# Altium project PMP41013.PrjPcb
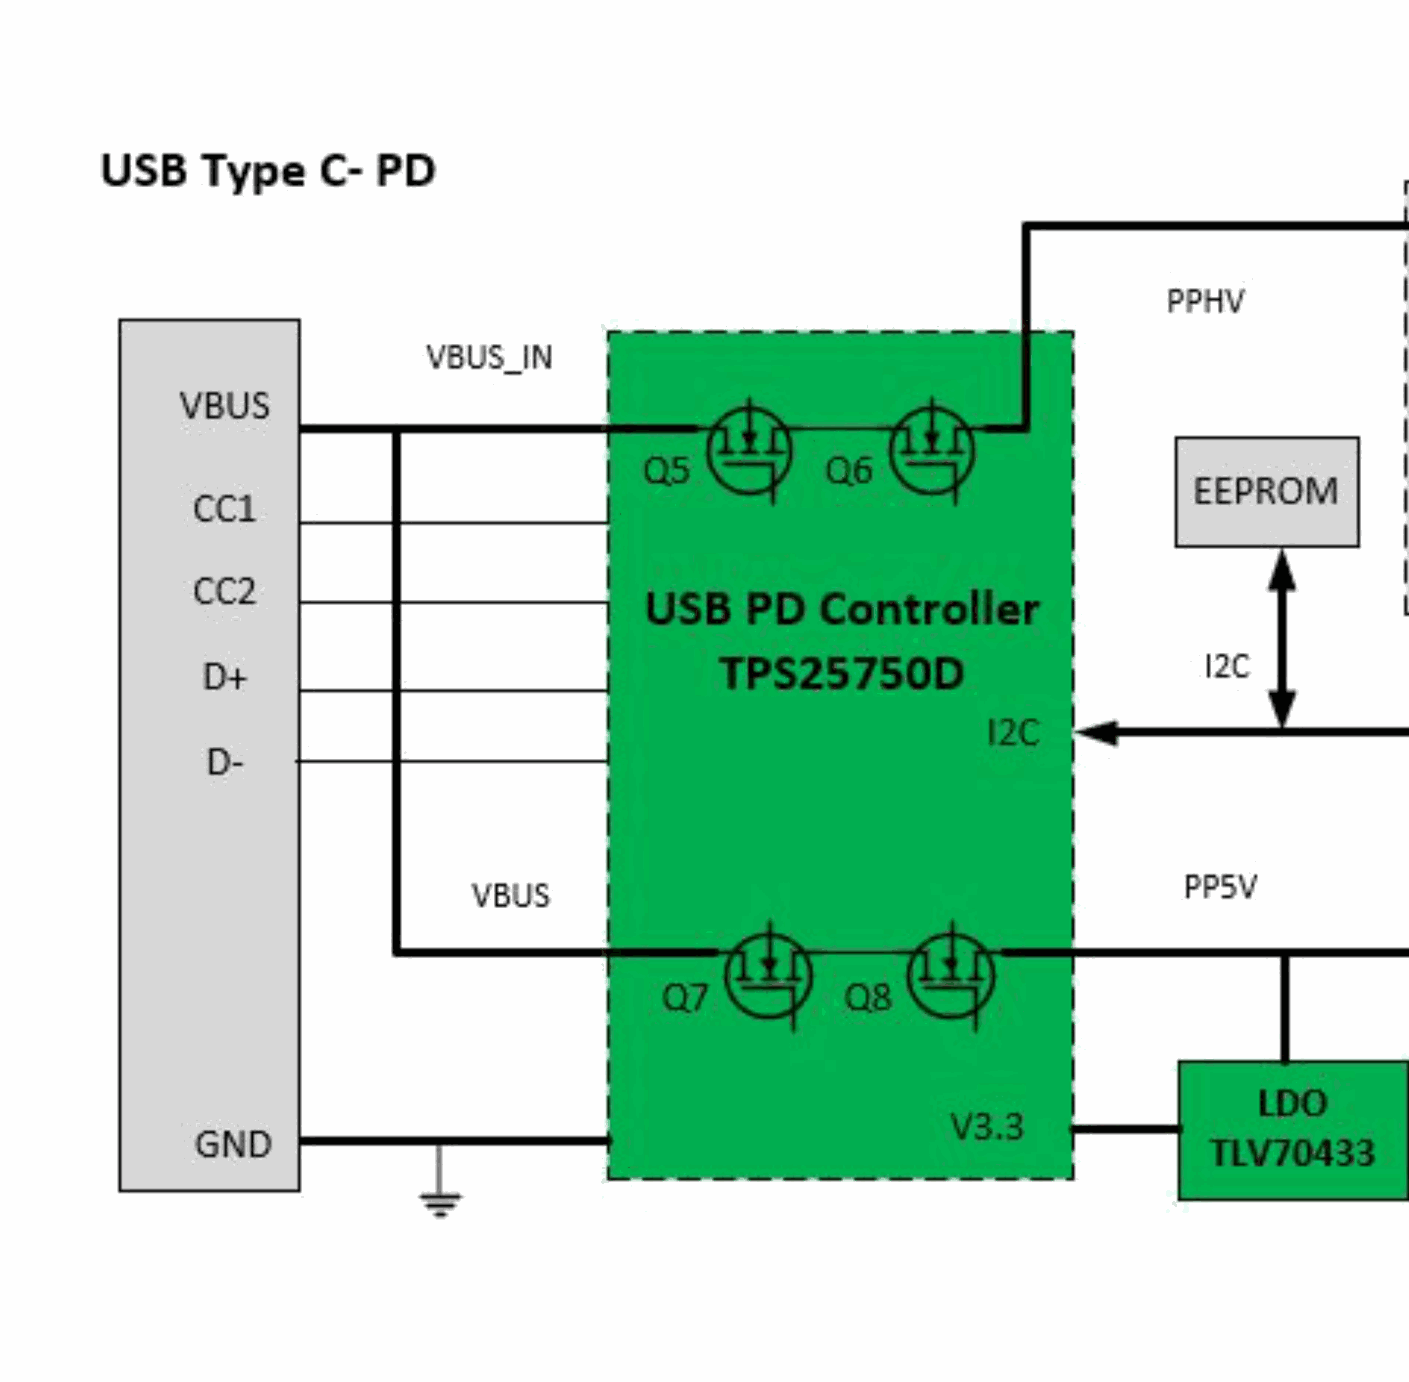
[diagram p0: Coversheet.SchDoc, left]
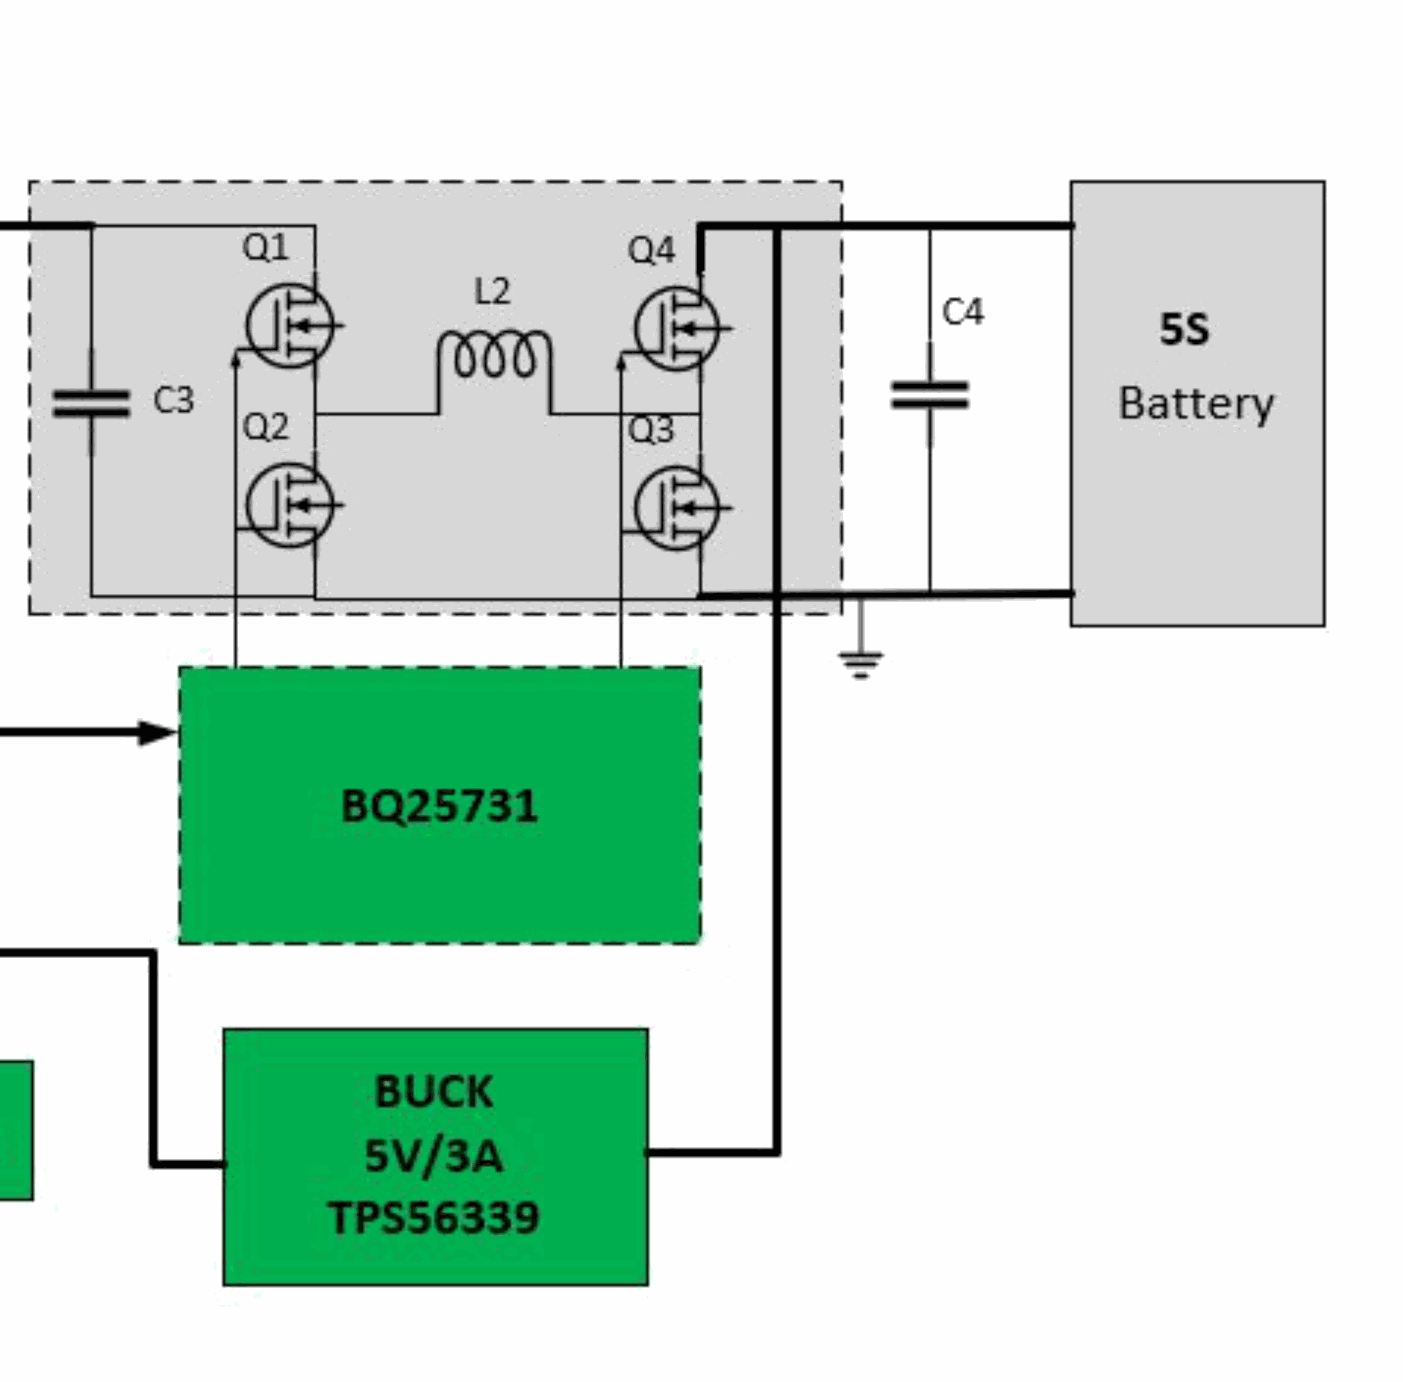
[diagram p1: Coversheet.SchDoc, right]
TID: N/A; TechSupport: http://www.ti.com/support; SCH_Rev: E1; PRJ_Title: 5S Bi-directional USB Type C PD charger; PRJ_Number: PMP41013; PRJ_Engineer: Max Wang; PRJ_Customer: Public Release; PCB_Rev: E1; PCB_Layout: Max Wang; CopyrightYear: 2018
4 sheets, 135 parts. Net scope: global (net labels, ports and power ports of the same name join across sheets).
Board file: PMP41013.PcbDoc
Sheets:
  Coversheet.SchDoc
  BQ25731 Charger.SchDoc
  TPS25750 USB PD Control.SchDoc
  PMP41013_Hardware.SchDoc

## Sheet Coversheet.SchDoc
size A2; Date: Not shown in title block; ApprovedBy: Not shown in title block; CheckedBy: Not shown in title block; Author: Not shown in title block; CompanyName: Not shown in title block; Engineer: Not shown in title block; Organization: Not shown in title block; Address1: Not shown in title block; Address2: Not shown in title block; Address3: Not shown in title block; Address4: Not shown in title block; DocumentNumber: 2; Revision: Use project parameter SCH_Rev; SheetNumber: 2; SheetTotal: 3; PageSetup: Record=PageOptions¦CenterHorizontal=True¦CenterVertical=True¦PrintScale=1.00¦XCorrection=1.00¦YCorrection=1.00¦PrintKind=0¦BorderSize=5000000¦LeftOffset=0¦BottomOffset=0¦Orientation=2¦PaperLength=1000¦PaperWidth=1000¦Scale=100¦PaperSource=15¦PrintQuality=600¦MediaType=1¦DitherType=10¦PaperKind=Letter¦PrintScaleMode=1

## Sheet BQ25731 Charger.SchDoc
size A2; DrawnBy: Max Wang; Engineer: Max Wang; PageSetup: Record=PageOptions¦CenterHorizontal=True¦CenterVertical=True¦PrintScale=0.69¦XCorrection=1.00¦YCorrection=1.00¦PrintKind=0¦BorderSize=5000000¦LeftOffset=0¦BottomOffset=0¦Orientation=2¦PaperLength=1000¦PaperWidth=1000¦Scale=100¦PaperSource=15¦PrintQuality=600¦MediaType=1¦DitherType=10¦PaperKind=Letter¦PrintScaleMode=1
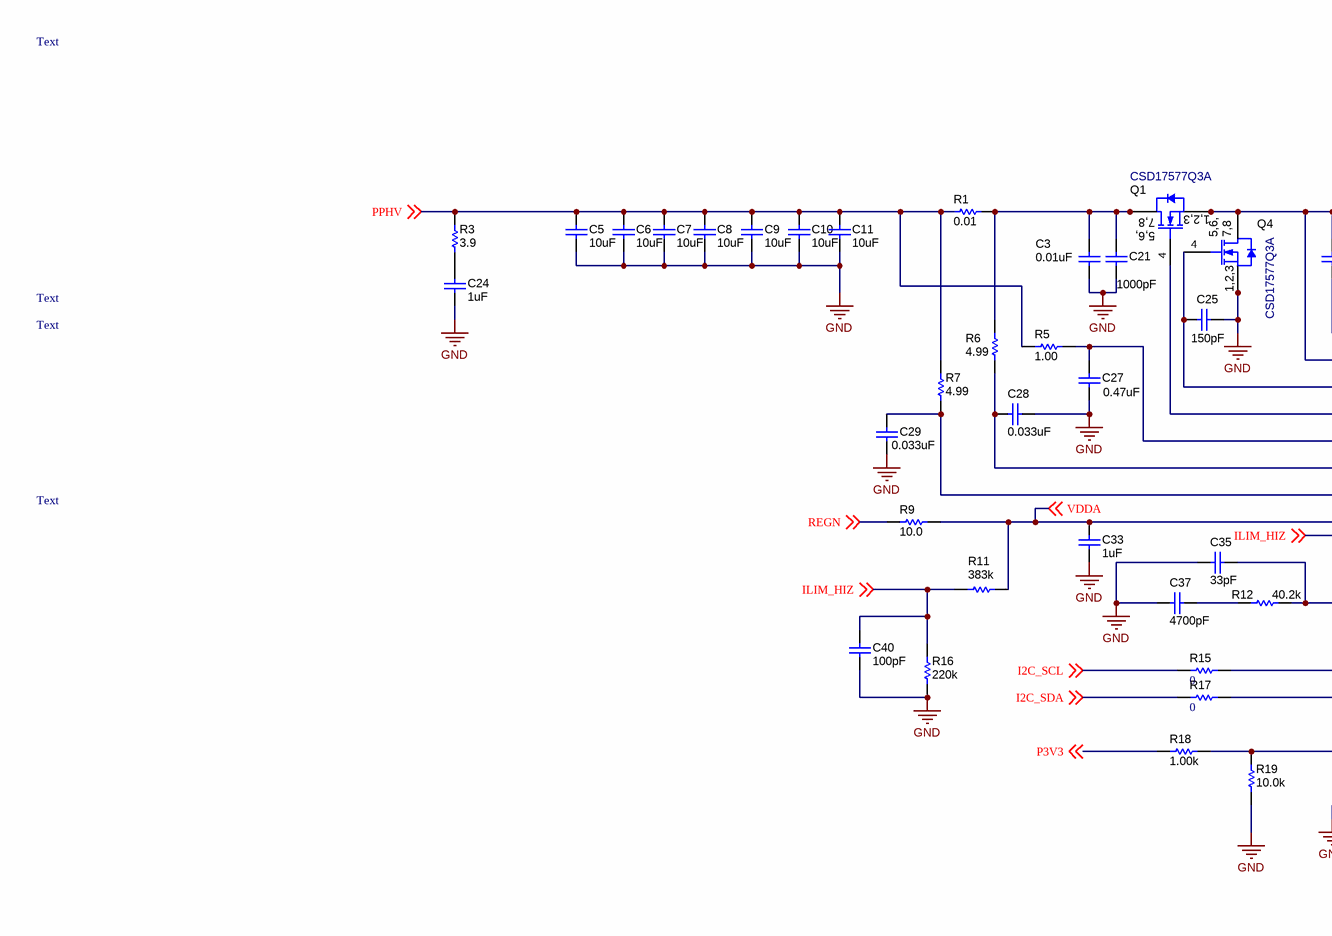
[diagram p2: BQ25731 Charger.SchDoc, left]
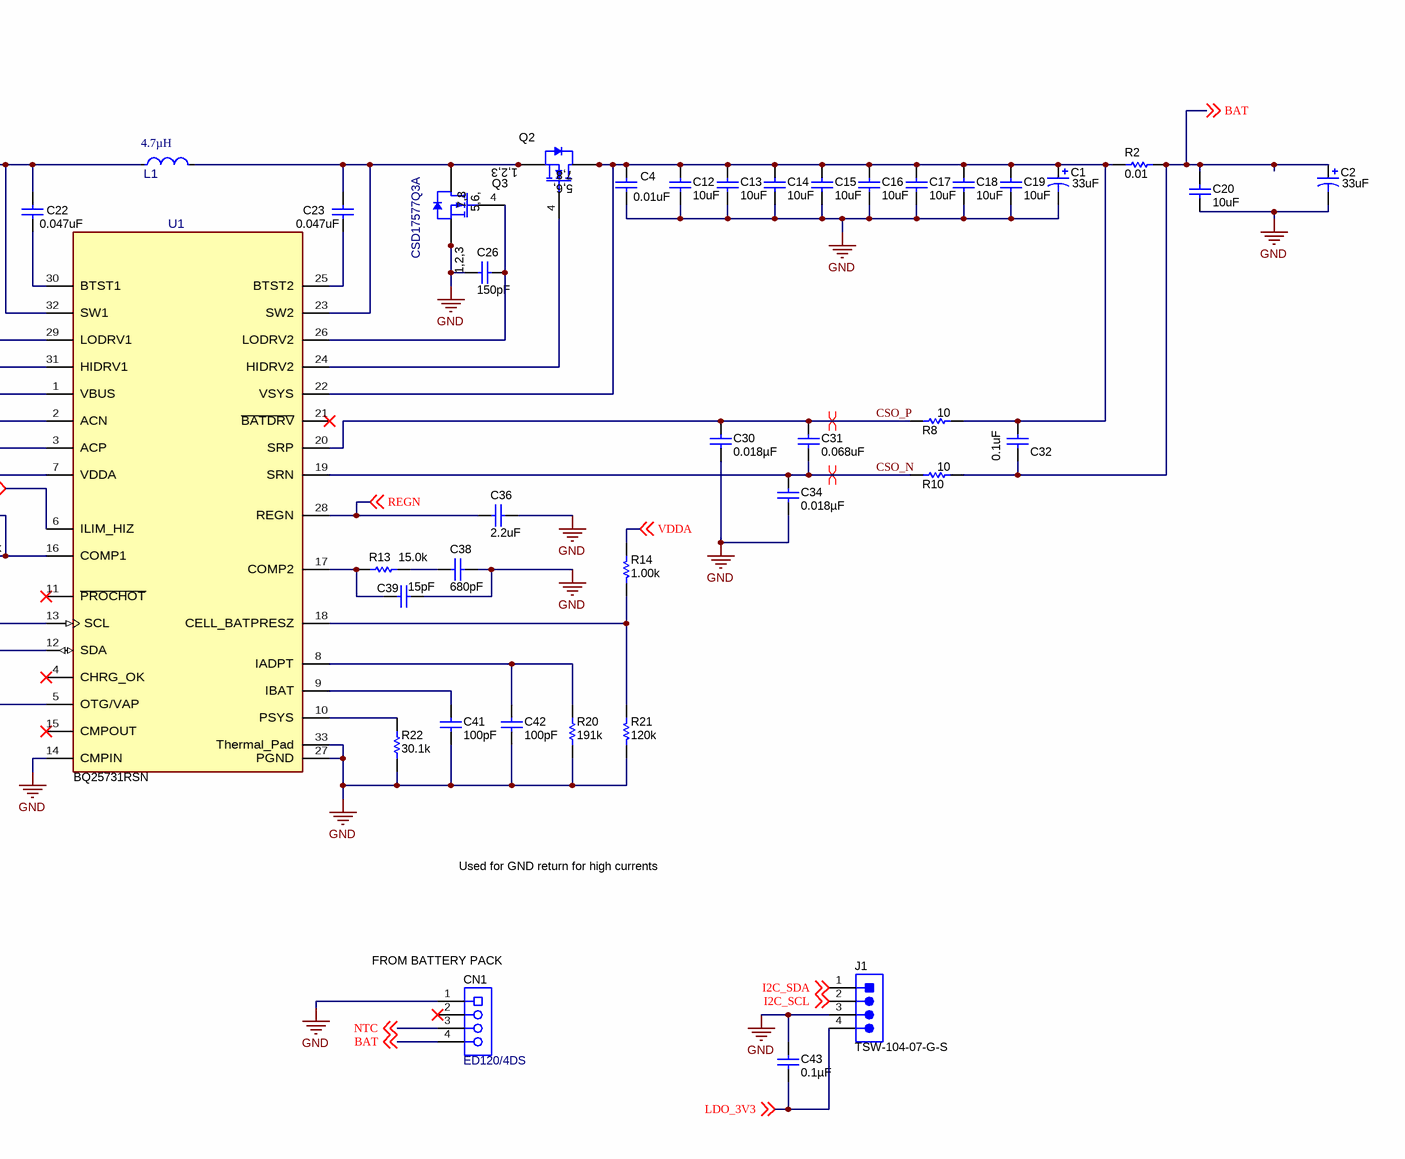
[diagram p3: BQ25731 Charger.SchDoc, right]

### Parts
C1  ValueDisplayed: 33uF  [7343-31]  (hidden comment: Capacitor)
C2  ValueDisplayed: 33uF  [7343-31]  (hidden comment: Capacitor)
C3  ValueDisplayed: 0.01uF  [0603]  (hidden comment: T521D336M035ATE065)
C4  ValueDisplayed: 0.01uF  [0603]  (hidden comment: T521D336M035ATE065)
C5  ValueDisplayed: 10uF  [0603M]  (hidden comment: Capacitor)
C6  ValueDisplayed: 10uF  [0603M]  (hidden comment: Capacitor)
C7  ValueDisplayed: 10uF  [0603M]  (hidden comment: Capacitor)
C8  ValueDisplayed: 10uF  [0603M]  (hidden comment: Capacitor)
C9  ValueDisplayed: 10uF  [0603M]  (hidden comment: Capacitor)
C10  ValueDisplayed: 10uF  [0603M]  (hidden comment: Capacitor)
C11  ValueDisplayed: 10uF  [0603M]  (hidden comment: Capacitor)
C12  ValueDisplayed: 10uF  [0603M]  (hidden comment: Capacitor)
C13  ValueDisplayed: 10uF  [0603M]  (hidden comment: Capacitor)
C14  ValueDisplayed: 10uF  [0603M]  (hidden comment: Capacitor)
C15  ValueDisplayed: 10uF  [0603M]  (hidden comment: Capacitor)
C16  ValueDisplayed: 10uF  [0603M]  (hidden comment: Capacitor)
C17  ValueDisplayed: 10uF  [0603M]  (hidden comment: Capacitor)
C18  ValueDisplayed: 10uF  [0603M]  (hidden comment: Capacitor)
C19  ValueDisplayed: 10uF  [0603M]  (hidden comment: Capacitor)
C20  ValueDisplayed: 10uF  [0603M]  (hidden comment: Capacitor)
C21  ValueDisplayed: 1000pF  [0402L]  (hidden comment: Capacitor)
C22  ValueDisplayed: 0.047uF  [0603L]  (hidden comment: Capacitor)
C23  ValueDisplayed: 0.047uF  [0603L]  (hidden comment: Capacitor)
C24  ValueDisplayed: 1uF  [0603L]  (hidden comment: Capacitor)
C25  ValueDisplayed: 150pF  [0402]  (hidden comment: 885012005062)
C26  ValueDisplayed: 150pF  [0603L]  (hidden comment: Capacitor)
C27  ValueDisplayed: 0.47uF  [0603]  (hidden comment: C1608X5R1H474K080AB)
C28  ValueDisplayed: 0.033uF  [0603L]  (hidden comment: Capacitor)
C29  ValueDisplayed: 0.033uF  [0603L]  (hidden comment: Capacitor)
C30  ValueDisplayed: 0.018µF  [0603M]  (hidden comment: GRM188R71H183KA01D)
C31  ValueDisplayed: 0.068uF  [0402]  (hidden comment: GRM155R61A683KA01D)
C32  ValueDisplayed: 0.1uF  [0603L]  (hidden comment: Capacitor)
C33  ValueDisplayed: 1uF  [0603L]  (hidden comment: Capacitor)
C34  ValueDisplayed: 0.018µF  [0603M]  (hidden comment: GRM188R71H183KA01D)
C35  ValueDisplayed: 33pF  [0402L]  (hidden comment: Capacitor)
C36  ValueDisplayed: 2.2uF  [0603L]  (hidden comment: Capacitor)
C37  ValueDisplayed: 4700pF  [0402]  (hidden comment: 885012205029)
C38  ValueDisplayed: 680pF  [0402L]  (hidden comment: Capacitor)
C39  ValueDisplayed: 15pF  [0402L]  (hidden comment: Capacitor)
C40  ValueDisplayed: 100pF  [0603L]  (hidden comment: Capacitor)
C41  ValueDisplayed: 100pF  [0603L]  (hidden comment: Capacitor)
C42  ValueDisplayed: 100pF  [0603L]  (hidden comment: Capacitor)
C43  ValueDisplayed: 0.1µF  [0603]  (hidden comment: 0603YC104JAT2A)
CN1  ED120/4DS  [On-Shore_ED120_4DS]
J1  TSW-104-07-G-S  [TSW-104-07-G-S]
L1  Ind_H: 4.7µH  [FP-BMQADY1010404R7MA1_SMD2-MFG]  (hidden comment: BMQADY1010404R7MA1)
Q1  CSD17577Q3A  [DNH0008A]
Q2  CSD17577Q3A  [DNH0008A]  (value not drawn)
Q3  CSD17577Q3A  [DNH0008A]
Q4  CSD17577Q3A  [DNH0008A]
R1  value 0.01  [1206]  (hidden comment: Resistor)
R2  value 0.01  [1206]  (hidden comment: Resistor)
R3  ValueDisplayed: 3.9  [1206]  (hidden comment: CRCW12063R90JNEA)
R5  ValueDisplayed: 1.00  [0603]  (hidden comment: RC0603FR-071RL)
R6  ValueDisplayed: 4.99  [0603L]  (hidden comment: Resistor)
R7  ValueDisplayed: 4.99  [0603L]  (hidden comment: Resistor)
R8  ValueDisplayed: 10  [0603L]  (hidden comment: Resistor)
R9  value 10.0  [0603L]  (hidden comment: Resistor)
R10  ValueDisplayed: 10  [0603L]  (hidden comment: Resistor)
R11  ValueDisplayed: 383k  [0603L]  (hidden comment: Resistor)
R12  ValueDisplayed: 40.2k  [0402L]  (hidden comment: Resistor)
R13  ValueDisplayed: 15.0k  [0402]  (hidden comment: CRCW040215K0FKED)
R14  ValueDisplayed: 1.00k  [0603]  (hidden comment: CRCW06031K00FKEA)
R15  ValueDisplayed: 0  [0603]  (hidden comment: RMCF0603ZT0R00)
R16  ValueDisplayed: 220k  [0603L]  (hidden comment: RC0603FR-07220KL)
R17  ValueDisplayed: 0  [0603]  (hidden comment: RMCF0603ZT0R00)
R18  ValueDisplayed: 1.00k  [0402]  (hidden comment: CRCW04021K00FKED)
R19  ValueDisplayed: 10.0k  [0603]  (hidden comment: CRCW060310K0FKEA)
R20  ValueDisplayed: 191k  [0603]  (hidden comment: CRCW0603191KFKEA)
R21  ValueDisplayed: 120k  [0603L]  (hidden comment: RC0603FR-07120KL)
R22  value 30.1k  [0603L]  (hidden comment: Resistor)
U1  BQ25731RSN  [RSN0032B-MFG]

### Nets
GND: C1.2(-) C2.2(-) C3.2 C4.2 C5.2 C6.2 C7.2 C8.2 C9.2 C10.2 C11.2 C12.2 C13.2 C14.2 C15.2 C16.2 C17.2 C18.2 C19.2 C20.2 C21.2 C24.2 C25.1 C26.1 C27.2 C28.1 C29.2 C30.2 C33.2 C34.2 C35.1 C36.2 C37.2 C38.2 C39.2 C40.2 C41.2 C42.2 C43.1 CN1.1 J1.3 Q3.1(S) Q3.2(S) Q3.3(S) Q4.1(S) Q4.2(S) Q4.3(S) R16.2 R19.1 R20.1 R21.1 R22.2 U1.14(CMPIN) U1.27(PGND) U1.33(Thermal_Pad)
BAT: C2.1(+) C20.1 C32.2 CN1.4 R2.2 R10.1 ; off-sheet BAT
CSO_N: C31.2 C34.1 R10.2 U1.19(SRN)
CSO_P: C30.1 C31.1 R8.2 U1.20(SRP)
I2C_SCL: J1.2 R15.1 ; off-sheet I2C_SCL
I2C_SDA: J1.1 R17.1 ; off-sheet I2C_SDA
ILIM_HIZ: C40.1 R11.2 R16.1 U1.6(ILIM_HIZ) ; off-sheet ILIM_HIZ
LDO_3V3: C43.2 J1.4 ; off-sheet LDO_3V3
NTC: CN1.3 ; off-sheet NTC
P3V3: R18.1 ; off-sheet P3V3
PPHV: C5.1 C6.1 C7.1 C8.1 C9.1 C10.1 C11.1 R1.1 R3.2 R5.1 R7.2 ; off-sheet PPHV
REGN: C36.1 R9.1 U1.28(REGN) ; off-sheet REGN
VDDA: C33.1 R9.2 R11.1 R14.2 U1.7(VDDA) ; off-sheet VDDA
NetC1_1: C1.1(+) C4.1 C12.1 C13.1 C14.1 C15.1 C16.1 C17.1 C18.1 C19.1 C32.1 Q2.5(D) Q2.6(D) Q2.7(D) Q2.8(D) Q2.9(D) R2.1 R8.1 U1.22(VSYS)
NetC3_1: C3.1 C21.1 Q1.5(D) Q1.6(D) Q1.7(D) Q1.8(D) Q1.9(D) R1.2 R6.2
NetC22_1: C22.1 U1.30(BTST1)
NetC22_2: C22.2 L1.1 Q1.1(S) Q1.2(S) Q1.3(S) Q4.5(D) Q4.6(D) Q4.7(D) Q4.8(D) Q4.9(D) U1.32(SW1)
NetC23_1: C23.1 U1.25(BTST2)
NetC23_2: C23.2 L1.2 Q2.1(S) Q2.2(S) Q2.3(S) Q3.5(D) Q3.6(D) Q3.7(D) Q3.8(D) Q3.9(D) U1.23(SW2)
NetC24_1: C24.1 R3.1
NetC25_2: C25.2 Q4.4(G) U1.29(LODRV1)
NetC26_2: C26.2 Q3.4(G) U1.26(LODRV2)
NetC27_1: C27.1 R5.2 U1.1(VBUS)
NetC28_2: C28.2 R6.1 U1.2(ACN)
NetC29_1: C29.1 R7.1 U1.3(ACP)
NetC35_2: C35.2 R12.2 U1.16(COMP1)
NetC37_1: C37.1 R12.1
NetC38_1: C38.1 R13.2
NetC39_1: C39.1 R13.1 U1.17(COMP2)
NetC41_1: C41.1 U1.9(IBAT)
NetC42_1: C42.1 R20.2 U1.8(IADPT)
NetQ1_4: Q1.4(G) U1.31(HIDRV1)
NetQ2_4: Q2.4(G) U1.24(HIDRV2)
NetR14_1: R14.1 R21.2 U1.18(CELL_BATPRESZ)
NetR15_2: R15.2 U1.13(SCL)
NetR17_2: R17.2 U1.12(SDA)
NetR18_2: R18.2 R19.2 U1.5(OTG/VAP)
NetR22_1: R22.1 U1.10(PSYS)

Not connected (* = marked no-connect by the designer): CN1 2*; U1 4(CHRG_OK)* 11(~{PROCHOT})* 15(CMPOUT)* 21(~{BATDRV})*

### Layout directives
differential pair: CSO_N, CSO_P

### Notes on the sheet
- Text
- Used for GND return for high currents
- (near CN1) FROM BATTERY PACK

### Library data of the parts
C1 C2 = CMP-0011849-2: CAP, TA, 33 uF, 35 V, +/- 20%, 0.065 ohm, SMD; Manufacturer: Kemet; PartNumber: T521D336M035ATE065; TaMin_C: -55°C; ESR_ohm: 0.065; Polarized: Y; SizeAreaWB_mm2: 58.59; U/M: EA; Value: 33uF; TaMax_C: 125°C; SizeZ_mm: 3.1; SizeX_mm: 7.3; SizeY_mm: 4.3; Value2: 35V; SizeArea_mm2: 31.39; AEC Qualified: N; Cap_F: 33µF; IRMS_A: 1.9A; AEC Category: Q200
C3 = CMP-0007403-4: CAP, CERM, 0.01 uF, 25 V, +/- 10%, X7R, 0603; PartNumber: GRM188R71E103KA01D; Manufacturer: MuRata; Polarized: N; Value: 0.01uF; U/M: EA; Cap_F: 10nF; Value1: Unknown; VDC_V: 25V; TaMin_C: -55°C; TaMax_C: 125°C; AEC Category: Q200; SizeAreaWB_mm2: 4.68; SizeZ_mm: 1; SizeX_mm: 1.6; SizeY_mm: 0.8; SizeArea_mm2: 1.28
C4 = CMP-0007403-4: CAP, CERM, 0.01 uF, 25 V, +/- 10%, X7R, 0603; PartNumber: GRM188R71E103KA01D; Manufacturer: MuRata; Polarized: N; Value: 0.01uF; U/M: EA; Cap_F: 10nF; Value1: Unknown; VDC_V: 25V; TaMin_C: -55°C; TaMax_C: 125°C; SizeAreaWB_mm2: 4.68; SizeZ_mm: 1; SizeX_mm: 1.6; SizeY_mm: 0.8; SizeArea_mm2: 1.28; AEC Category: Q200
C5-C20 = CMP-0007344-5: CAP, CERM, 10 uF, 25 V, +/- 20%, X5R, 0603; Manufacturer: MuRata; PartNumber: GRM188R61E106MA73D; TaMin_C: -55°C; Polarized: N; SizeAreaWB_mm2: 4.68; Value1: Unknown; U/M: EA; Value: 10uF; TaMax_C: 85°C; SizeZ_mm: 1; SizeX_mm: 1.6; SizeY_mm: 0.8; Cap_Case: 0603; Value2: 25V; SizeArea_mm2: 1.28; Cap_F: 10µF; AEC Category: Q200
C21 = CMP-0006234-2: CAP, CERM, 1000 pF, 25 V, +/- 5%, X7R, 0402; PartNumber: C0402C102J3RACTU; Manufacturer: Kemet; Polarized: N; Value: 1000pF; U/M: EA; Cap_F: 1nF; Value1: Unknown; VDC_V: 25V; TaMin_C: -55°C; TaMax_C: 125°C; Cap_Case: 0402; SizeAreaWB_mm2: 3; SizeZ_mm: 0.6; SizeX_mm: 1; SizeY_mm: 0.5; AEC Category: Q200
C22 C23 = CMP-0007423-4: CAP, CERM, 0.047 uF, 25 V, +/- 10%, X7R, 0603; PartNumber: GRM188R71E473KA01D; Manufacturer: MuRata; Polarized: N; U/M: EA; Cap_F: 47nF; Value1: Unknown; VDC_V: 25V; TaMin_C: -55°C; TaMax_C: 125°C; Cap_Case: 0603; SizeAreaWB_mm2: 4.68; SizeZ_mm: 1; SizeX_mm: 1.6; SizeY_mm: 0.8; SizeArea_mm2: 1.28; AEC Category: Q200
C24 C33 = CMP-0007405-4: CAP, CERM, 1 uF, 25 V, +/- 10%, X7R, 0603; PartNumber: GRM188R71E105KA12D; Manufacturer: MuRata; Polarized: N; Value: 1uF; U/M: EA; Cap_F: 1µF; Value1: Unknown; VDC_V: 25V; TaMin_C: -55°C; TaMax_C: 125°C; Cap_Case: 0603; SizeAreaWB_mm2: 4.68; SizeZ_mm: 1; SizeX_mm: 1.6; SizeY_mm: 0.8; SizeArea_mm2: 1.28; AEC Category: Q200
C25 = CMP-0064913-2: CAP, CERM, 150 pF, 50 V,+/- 5%, C0G/NP0, 0402; Manufacturer: Wurth Elektronik; TaMin_C: -55°C; Polarized: N; SizeAreaWB_mm2: 3; Value1: Unknown; U/M: EA; Value: 150pF; TaMax_C: 125°C; SizeZ_mm: 0.6; SizeX_mm: 1; SizeY_mm: 0.5; Value2: 50V; AEC Category: Q200
C26 = CMP-0006880-4: CAP, CERM, 150 pF, 50 V, +/- 5%, C0G/NP0, 0603; PartNumber: C0603C151J5GACTU; Manufacturer: Kemet; Polarized: N; Value: 150pF; U/M: EA; Value1: Unknown; VDC_V: 50V; TaMin_C: -55°C; TaMax_C: 125°C; Cap_Case: 0603; AEC Category: Q200; SizeAreaWB_mm2: 4.68; SizeZ_mm: 1; SizeX_mm: 1.6; SizeY_mm: 0.8; SizeArea_mm2: 1.28
C27 = CMP-0007016-5: CAP, CERM, 0.47 uF, 50 V, +/- 10%, X5R, 0603; Manufacturer: TDK; TaMin_C: -55°C; ESR_ohm: 0.010974; Polarized: N; SizeAreaWB_mm2: 4.68; Value1: 0.010974 ohm; U/M: EA; Value: 0.47uF; TaMax_C: 85°C; SizeZ_mm: 1; SizeX_mm: 1.6; SizeY_mm: 0.8; Value2: 50V; SizeArea_mm2: 1.28; Cap_F: 470nF; IRMS_A: 1.57483A; AEC Category: Q200
C28 C29 = CMP-0007419-4: CAP, CERM, 0.033 uF, 25 V, +/- 10%, X7R, 0603; PartNumber: GRM188R71E333KA01D; Manufacturer: MuRata; Polarized: N; U/M: EA; Cap_F: 33nF; Value1: Unknown; VDC_V: 25V; TaMin_C: -55°C; TaMax_C: 125°C; Cap_Case: 0603; AEC Category: Q200; SizeArea_mm2: 1.28; SizeAreaWB_mm2: 4.68; SizeX_mm: 1.6; SizeY_mm: 0.8; SizeZ_mm: 1
C30 C34 = GRM188R71H183KA01D: CAP, CERM, 0.018 µF, 50 V,+/- 10%, X7R, 0603; Manufacturer: MuRata; Polarized: N; CompType: Capacitor; Value: 0.018uF; U/M: EA; Cap_F: 0.000000018; Tolerance_%: 10; VDC_V: 50; Value2: 50V; TaMin_C: -55; TaMax_C: 125; Cap_Case: 0603; SizeArea_mm2: 1.28; SizeAreaWB_mm2: 4.68; SizeX_mm: 1.6; SizeY_mm: 0.8; SizeZ_mm: 1; AEC Category: Q200
C31 = CMP-0006585-2: CAP, CERM, 0.068 uF, 10 V, +/- 10%, X5R, 0402; Manufacturer: MuRata; TaMin_C: -55°C; Polarized: N; SizeAreaWB_mm2: 3; Value1: Unknown; U/M: EA; TaMax_C: 85°C; SizeZ_mm: 0.6; SizeX_mm: 1; SizeY_mm: 0.5; Value2: 10V; Cap_F: 68nF; AEC Category: Q200
C32 = CMP-0007404-4: CAP, CERM, 0.1 uF, 25 V, +/- 10%, X7R, 0603; PartNumber: GRM188R71E104KA01D; Manufacturer: MuRata; Polarized: N; Value: 0.1uF; U/M: EA; Cap_F: 100nF; Value1: Unknown; VDC_V: 25V; TaMin_C: -55°C; TaMax_C: 125°C; Cap_Case: 0603; SizeAreaWB_mm2: 4.68; SizeZ_mm: 1; SizeX_mm: 1.6; SizeY_mm: 0.8; SizeArea_mm2: 1.28; AEC Category: Q200
C35 = CMP-0006454-2: CAP, CERM, 33 pF, 50 V, +/- 5%, C0G/NP0, 0402; PartNumber: GRM1555C1H330JA01D; Manufacturer: MuRata; Polarized: N; Value: 33pF; U/M: EA; Value1: Unknown; VDC_V: 50V; TaMin_C: -55°C; TaMax_C: 125°C; Cap_Case: 0402; AEC Category: Q200; SizeArea_mm2: 0.5; SizeAreaWB_mm2: 3; SizeX_mm: 1; SizeZ_mm: 0.6
C36 = CMP-0007356-5: CAP, CERM, 2.2 uF, 35 V, +/- 10%, X5R, 0603; PartNumber: GRM188R6YA225KA12D; Manufacturer: MuRata; Polarized: N; Value: 2.2uF; U/M: EA; Cap_F: 2.2µF; Value1: Unknown; VDC_V: 35V; TaMin_C: -55°C; TaMax_C: 85°C; Cap_Case: 0603; SizeAreaWB_mm2: 4.68; SizeZ_mm: 1; SizeX_mm: 1.6; SizeY_mm: 0.8; SizeArea_mm2: 1.28; AEC Category: Q200
C37 = 885012205029: CAP, CERM, 4700 pF, 16 V,+/- 10%, X7R, 0402; Manufacturer: Wurth Elektronik; Polarized: N; CompType: Capacitor; Value: 4700pF; U/M: EA; Cap_F: 0.0000000047; Tolerance_%: 10; VDC_V: 16; Value2: 16V; TaMin_C: -55; TaMax_C: 125; SizeArea_mm2: 0.5; SizeAreaWB_mm2: 3; SizeX_mm: 1; SizeZ_mm: 0.6; AEC Category: Q200; Green_Lifecycle: Not Set; Green_REACh: Incomplete
C38 = CMP-0006486-2: CAP, CERM, 680 pF, 50 V, +/- 5%, C0G/NP0, 0402; PartNumber: GRM1555C1H681JA01D; Manufacturer: MuRata; Polarized: N; Value: 680pF; U/M: EA; Value1: Unknown; VDC_V: 50V; TaMin_C: -55°C; TaMax_C: 125°C; Cap_Case: 0402; AEC Category: Q200; SizeAreaWB_mm2: 3; SizeZ_mm: 0.6; SizeX_mm: 1; SizeY_mm: 0.5
C39 = CMP-0006420-2: CAP, CERM, 15 pF, 50 V, +/- 5%, C0G/NP0, 0402; PartNumber: GRM1555C1H150JA01D; Manufacturer: MuRata; Polarized: N; Value: 15pF; U/M: EA; Value1: Unknown; VDC_V: 50V; TaMin_C: -55°C; TaMax_C: 125°C; Cap_Case: 0402; AEC Category: Q200; SizeAreaWB_mm2: 3; SizeZ_mm: 0.6; SizeX_mm: 1; SizeY_mm: 0.5
C40-C42 = CMP-0006840-4: CAP, CERM, 100 pF, 50 V, +/- 5%, C0G/NP0, 0603; PartNumber: C0603C101J5GAC; Manufacturer: Kemet; Polarized: N; Value: 100pF; U/M: EA; Value1: Unknown; VDC_V: 50V; TaMin_C: -55°C; TaMax_C: 125°C; Cap_Case: 0603; SizeAreaWB_mm2: 4.68; SizeZ_mm: 1; SizeX_mm: 1.6; SizeY_mm: 0.8; SizeArea_mm2: 1.28; AEC Category: Q200
C43 = 0603YC104JAT2A: CAP, CERM, 0.1 µF, 16 V,+/- 5%, X7R, 0603; Manufacturer: AVX; Polarized: N; CompType: Capacitor; Value: 0.1uF; U/M: EA; Cap_F: 0.0000001; Tolerance_%: 5; ESR_ohm: 0.039; Value1: 0.039 ohm; VDC_V: 16; Value2: 16V; TaMin_C: -55; TaMax_C: 125; SizeArea_mm2: 1.28; SizeAreaWB_mm2: 4.68; SizeX_mm: 1.6; SizeY_mm: 0.8; SizeZ_mm: 1; AEC Category: Q200; Green_Lifecycle: Active; Green_REACh: Passed
CN1 = CMP-0074939-1: Terminal Block, 5.08 mm, 4x1, Brass, TH; Manufacturer: On-Shore Technology; Cert_VDE: Y; CNHeader: False; Current_A: 15A; Green_Lifecycle: Not Set; Shrouded: N; Gender: Female; Green_REACh: Incomplete; Voltage_V: 300V; Row_Count: 1; Pitch_mm: 5.08; CT: True
J1 = TSW-104-07-G-S: Header, 100mil, 4x1, Gold, TH; Manufacturer: Samtec; SymbolCreator: a0412235; Pitch_mm: 2.54; Gender: Male; Shrouded: N; Row_Count: 1; Current_A: 6.3; Voltage_V: 550; Cert_CSA: Y; Green_Lifecycle: Active; Green_REACh: Passed
L1 = CMP-0089507-1: 4700nH Shielded Molded Inductor Nonstandard; Manufacturer: Chilisin Electronics; SizeZ_mm: 4mm; Material: Magnetic Metal Powder; Tolerance_%: 20%; Irms: 11A; Test Frequency: 100kHz; DCR_ohm: 0.0105; Isat: 13A; AEC Qualified: No; Shrouded: true
Q1-Q4 = CMP-0000589-2: MOSFET, N-CH, 30 V, 19 A, DNH0008A (VSONP-8); Alternate Manufacturer: None; Manufacturer: Texas Instruments; SizeZ_mm: 0.9; ChType: N; Value2: 13 nC; Value1: 0.006; VdsMax_V: 30V; SizeX_mm: 3.3; Vgs_V: 20V; Value: 30V; Rdson45_ohm: 6.4m; SizeArea_mm2: 10.89; AEC Category: Q101; IdsMax_A: 19A; SizeAreaWB_mm2: 18.49; QgTyp_nC: 13; ChMode: Enhancement
R1 R2 = CMP-0018570-2: RES, 0.01, 1%, 1 W, 1206; PartNumber: WSLP1206R0100FEA; Manufacturer: Vishay-Dale; Value_Code: R010; Power_W: 1W; TempCo: 75 ppm/C; EIA_Code: E96; U/M: EA; SizeX_mm: 3.2; SizeY_mm: 1.6; SizeZ_mm: 1.35; SizeArea_mm2: 5.12; AEC Category: Q200
R3 = CMP-0018679-3: RES, 3.9, 5%, 0.25 W, AEC-Q200 Grade 0, 1206; Manufacturer: Vishay-Dale; Power_W: 250mW; TempCo: 200 ppm/C; Value_Code: 3R90; Value: 3.9; SizeX_mm: 3.2; SizeY_mm: 1.6; SizeZ_mm: 1.35; Value2: 0.25W; SizeArea_mm2: 5.12; AEC Qualified: Y; AEC Grade: 0; AEC Category: Q200; EIA_Code: E24; VDC_V: 200V
R5 = CMP-0022900-4: RES, 1.00, 1%, 0.1 W, 0603; Manufacturer: Yageo; Power_W: 100mW; TempCo: 200 ppm/C; Value_Code: 1R00; Value: 1.00; EIA_Code: E96; Res_ohm: 1; SizeX_mm: 1.6; SizeY_mm: 0.8; Value2: 0.1W; SizeArea_mm2: 1.28; AEC Qualified: N; VDC_V: 75V; AEC Category: Q200; SizeAreaWB_mm2: 4.68
R6 R7 = CMP-0022478-4: RES, 4.99, 1%, 0.1 W, AEC-Q200 Grade 0, 0603; PartNumber: CRCW06034R99FKEA; Manufacturer: Vishay-Dale; Value: 4.99; Value_Code: 4R99; Power_W: 100mW; Value2: 0.1W; VDC_V: 75V; TempCo: 100 ppm/C; EIA_Code: E96; U/M: EA; AEC Category: Q200; AEC Qualified: Y; AEC Grade: 0; SizeArea_mm2: 1.28; SizeX_mm: 1.6; SizeY_mm: 0.8; SizeZ_mm: 1
R8 R10 = CMP-0025703-4: RES, 10, 5%, 0.1 W, AEC-Q200 Grade 0, 0603; PartNumber: CRCW060310R0JNEA; Manufacturer: Vishay-Dale; Value: 10; Value_Code: 10R0; Power_W: 100mW; Value2: 0.1W; VDC_V: 75V; TempCo: 200 ppm/C; EIA_Code: E24; U/M: EA; SizeX_mm: 1.6; SizeY_mm: 0.8; SizeZ_mm: 1; SizeArea_mm2: 1.28; AEC Qualified: Y; AEC Category: Q200; AEC Grade: 0
R9 = CMP-0022003-4: RES, 10.0, 1%, 0.1 W, AEC-Q200 Grade 0, 0603; PartNumber: CRCW060310R0FKEA; Manufacturer: Vishay-Dale; Res_ohm: 10; Value_Code: 10R0; Power_W: 100mW; Value2: 0.1W; VDC_V: 75V; TempCo: 100 ppm/C; EIA_Code: E96; U/M: EA; SizeX_mm: 1.6; SizeY_mm: 0.8; SizeZ_mm: 1; SizeArea_mm2: 1.28; AEC Qualified: Y; AEC Category: Q200; AEC Grade: 0
R11 = CMP-0022362-4: RES, 383 k, 1%, 0.1 W, AEC-Q200 Grade 0, 0603; PartNumber: CRCW0603383KFKEA; Manufacturer: Vishay-Dale; Value: 383k; Power_W: 100mW; Value2: 0.1W; VDC_V: 75V; TempCo: 100 ppm/C; EIA_Code: E96; U/M: EA; SizeX_mm: 1.6; SizeY_mm: 0.8; SizeZ_mm: 1; SizeArea_mm2: 1.28; AEC Qualified: Y; AEC Category: Q200; AEC Grade: 0
R12 = CMP-0026367-2: RES, 40.2 k, 1%, 0.063 W, AEC-Q200 Grade 0, 0402; PartNumber: CRCW040240K2FKED; Manufacturer: Vishay-Dale; Value: 40.2k; Value_Code: 40k2; Power_W: 63mW; Value2: 0.063W; VDC_V: 50V; TempCo: 100 ppm/C; EIA_Code: E96; U/M: EA; AEC Category: Q200; AEC Qualified: Y; AEC Grade: 0; SizeX_mm: 1; SizeY_mm: 0.5; SizeZ_mm: 0.6
R13 = CRCW040215K0FKED: RES, 15.0 k, 1%, 0.063 W, 0402; Manufacturer: Vishay-Dale; CompType: Resistor; Value: 15.0k; Res_ohm: 15000; Value_Code: 15k0; Tolerance_%: 1; Power_W: 0.063; Value2: 0.063W; VDC_V: 50; TempCo: 100 ppm/C; SizeArea_mm2: 0.5; SizeZ_mm: 0.6; EIA_Code: E96; U/M: EA; AEC Category: Q200; Green_Lifecycle: Active; Green_REACh: Passed
R14 = CMP-0022109-5: RES, 1.00 k, 1%, 0.1 W, AEC-Q200 Grade 0, 0603; Manufacturer: Vishay-Dale; Value: 1.00k; Res_ohm: 1k; Value_Code: 1k00; Power_W: 100mW; Value2: 0.1W; VDC_V: 75V; TempCo: 100 ppm/C; EIA_Code: E96; SizeX_mm: 1.6; SizeY_mm: 0.8; SizeZ_mm: 1; SizeArea_mm2: 1.28; AEC Qualified: Y; AEC Category: Q200; AEC Grade: 0
R15 R17 = CMP-0023343-3: RES, 0, 1%, 0.1 W, AEC-Q200 Grade 0, 0603; Manufacturer: Stackpole Electronics Inc; Power_W: 100mW; TempCo: ppm/C; U/M: EA; Value: 0; SizeX_mm: 1.6; SizeY_mm: 0.8; SizeZ_mm: 1; Value2: 0.1W; SizeArea_mm2: 1.28; AEC Qualified: Y; AEC Category: Q200
R16 = CMP-0022917-4: RES, 220 k, 1%, 0.1 W, 0603; Manufacturer: Yageo; Value: 220k; Power_W: 100mW; Value2: 0.1W; VDC_V: 75V; TempCo: 100 ppm/C; SizeX_mm: 1.6; SizeY_mm: 0.8; SizeZ_mm: 1; SizeArea_mm2: 1.28; AEC Qualified: N; AEC Category: Q200; SizeAreaWB_mm2: 4.68
R18 = CRCW04021K00FKED: RES, 1.00 k, 1%, 0.063 W, 0402; Manufacturer: Vishay-Dale; CompType: Resistor; Value: 1.00k; Res_ohm: 1000; Value_Code: 1k00; Tolerance_%: 1; Power_W: 0.063; Value2: 0.063W; VDC_V: 50; TempCo: 100 ppm/C; SizeArea_mm2: 0.5; SizeZ_mm: 0.6; EIA_Code: E96; U/M: EA; AEC Category: Q200; Green_Lifecycle: Active; Green_REACh: Passed
R19 = CRCW060310K0FKEA: RES, 10.0 k, 1%, 0.1 W, 0603; Manufacturer: Vishay-Dale; CompType: Resistor; Value: 10.0k; Res_ohm: 10000; Value_Code: 10k0; Tolerance_%: 1; Power_W: 0.1; Value2: 0.1W; VDC_V: 75; TempCo: 100 ppm/C; SizeArea_mm2: 1.28; SizeX_mm: 1.6; SizeY_mm: 0.8; EIA_Code: E96; U/M: EA; AEC Category: Q200; Green_Lifecycle: Active; Green_REACh: Passed
R20 = CRCW0603191KFKEA: RES, 191 k, 1%, 0.1 W, 0603; Manufacturer: Vishay-Dale; CompType: Resistor; Value: 191k; Res_ohm: 191000; Tolerance_%: 1; Power_W: 0.1; Value2: 0.1W; VDC_V: 75; TempCo: 100 ppm/C; SizeArea_mm2: 1.28; SizeX_mm: 1.6; SizeY_mm: 0.8; EIA_Code: E96; U/M: EA; AEC Category: Q200; Green_Lifecycle: Active; Green_REACh: Passed
R21 = CMP-0022768-4: RES, 120 k, 1%, 0.1 W, 0603; Manufacturer: Yageo; Value: 120k; Power_W: 100mW; Value2: 0.1W; VDC_V: 75V; TempCo: 100 ppm/C; SizeX_mm: 1.6; SizeY_mm: 0.8; SizeZ_mm: 1; SizeArea_mm2: 1.28; AEC Qualified: N; AEC Category: Q200; SizeAreaWB_mm2: 4.68
R22 = CMP-0022324-4: RES, 30.1 k, 1%, 0.1 W, AEC-Q200 Grade 0, 0603; PartNumber: CRCW060330K1FKEA; Manufacturer: Vishay-Dale; Value_Code: 30k1; Power_W: 100mW; Value2: 0.1W; VDC_V: 75V; TempCo: 100 ppm/C; EIA_Code: E96; U/M: EA; SizeX_mm: 1.6; SizeY_mm: 0.8; SizeZ_mm: 1; SizeArea_mm2: 1.28; AEC Qualified: Y; AEC Category: Q200; AEC Grade: 0
U1 = CMP-0089013-3: No Description; Manufacturer: Texas Instruments; SizeZ_mm: 0.8mm; CompType: IC; AEC Category: Q200

## Sheet TPS25750 USB PD Control.SchDoc
size A2; DrawnBy: Max Wang; PageSetup: Record=PageOptions¦CenterHorizontal=True¦CenterVertical=True¦PrintScale=0.69¦XCorrection=1.00¦YCorrection=1.00¦PrintKind=0¦BorderSize=5000000¦LeftOffset=0¦BottomOffset=0¦Orientation=2¦PaperLength=1000¦PaperWidth=1000¦Scale=100¦PaperSource=15¦PrintQuality=600¦MediaType=1¦DitherType=10¦PaperKind=Letter¦PrintScaleMode=1
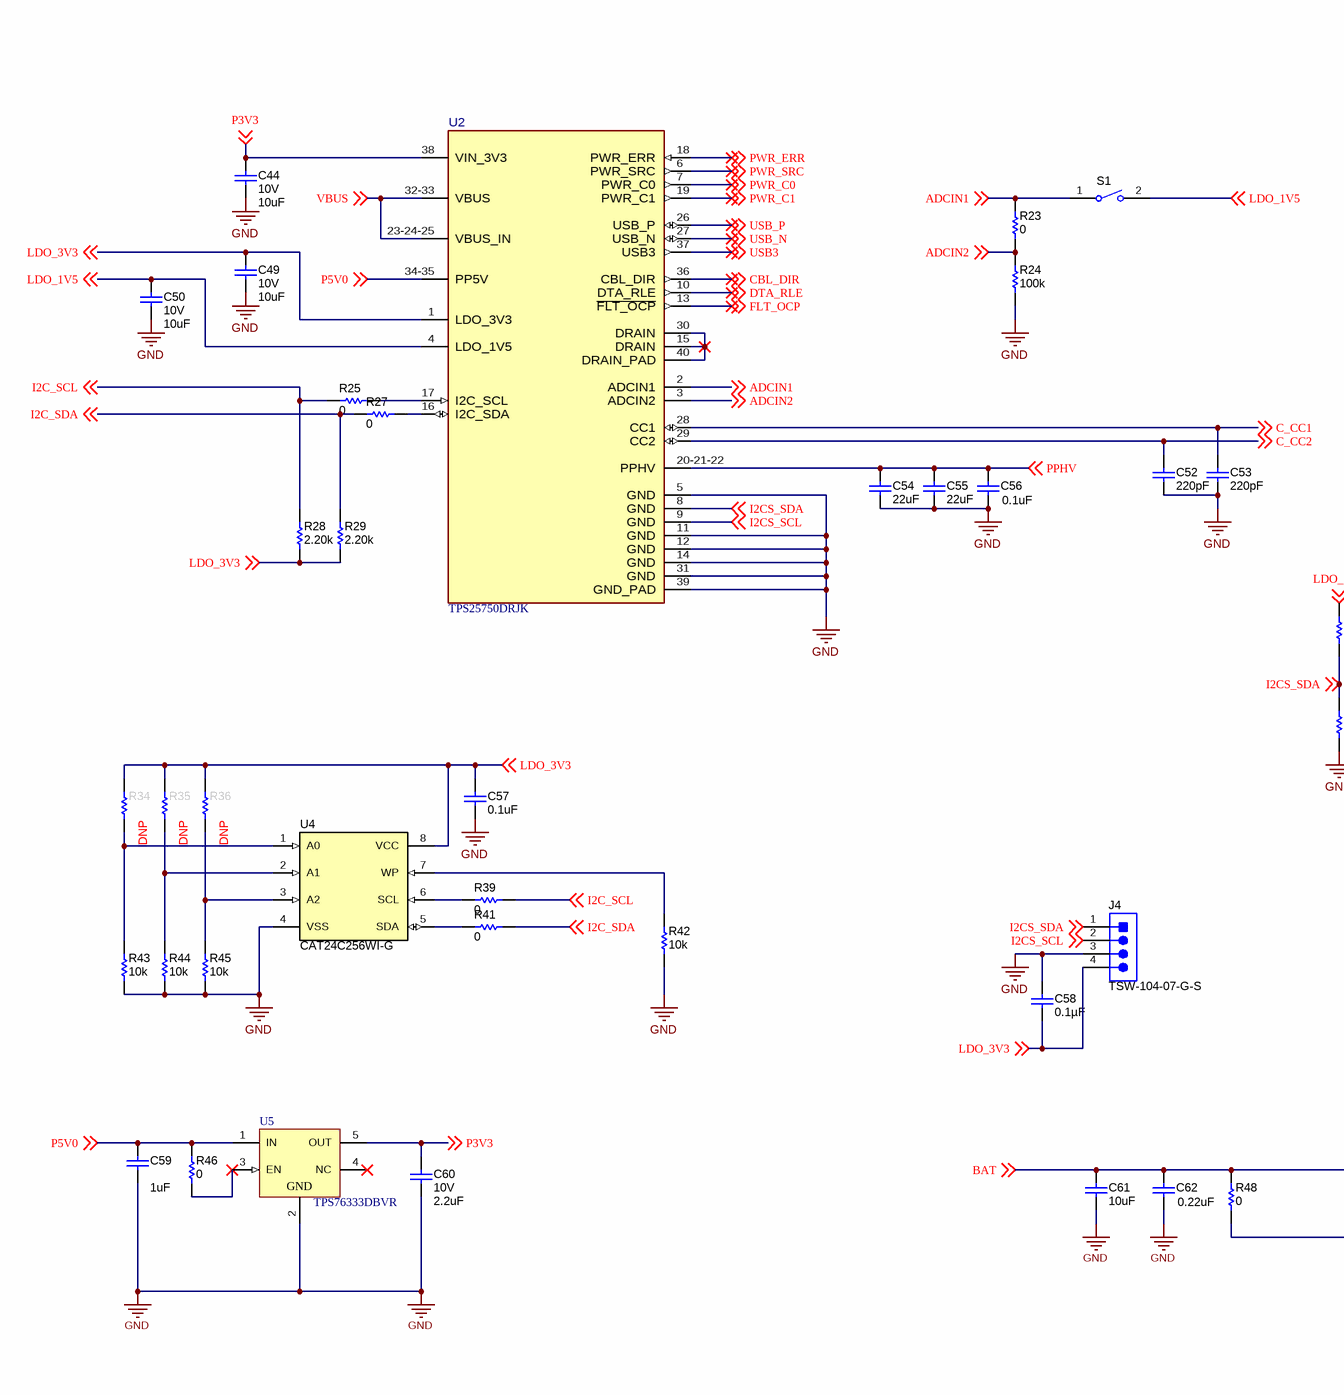
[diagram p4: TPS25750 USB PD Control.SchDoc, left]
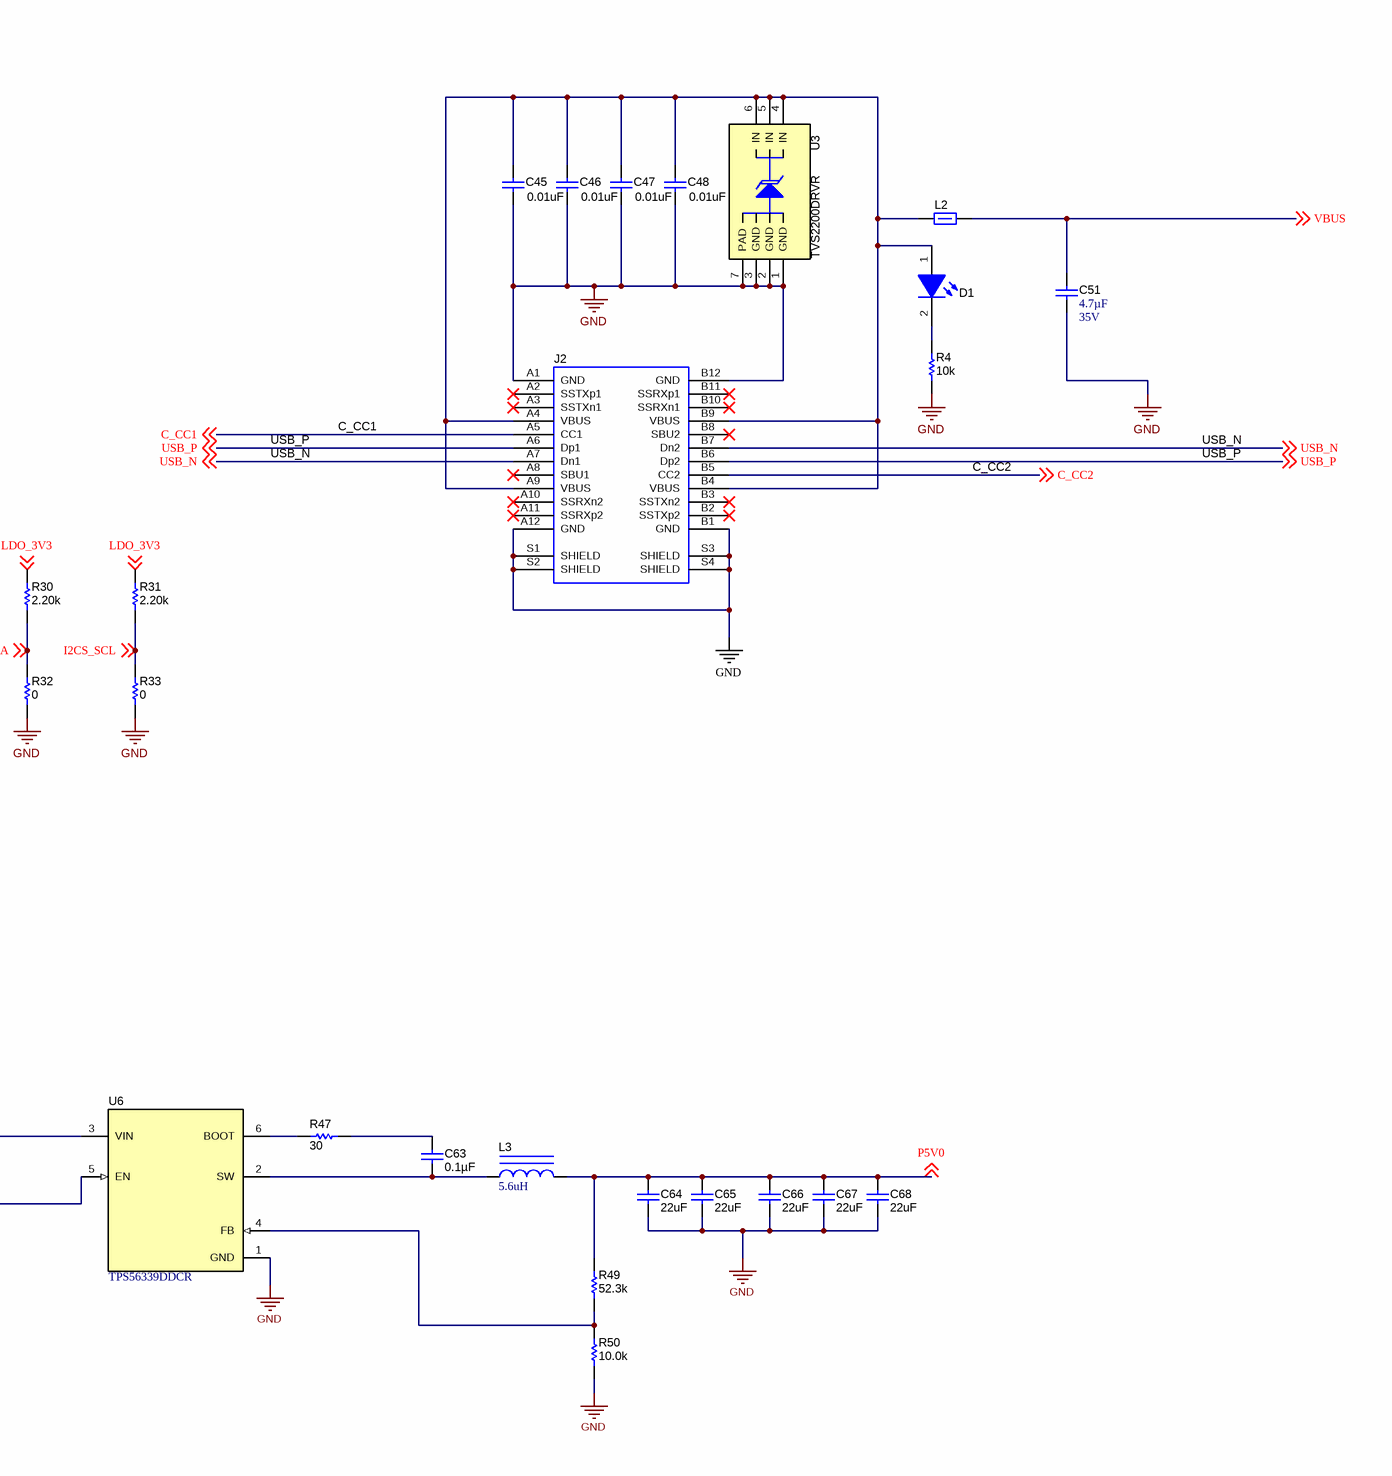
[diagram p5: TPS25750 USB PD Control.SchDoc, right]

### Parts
C44  VDC_V: 10V  ValueDisplayed: 10uF  [0402_070]  (hidden comment: CL05A106MP5NUNC)
C45  ValueDisplayed: 0.01uF  [0402]  (hidden comment: C0402C103J5RACTU)
C46  ValueDisplayed: 0.01uF  [0402]  (hidden comment: C0402C103J5RACTU)
C47  ValueDisplayed: 0.01uF  [0402]  (hidden comment: C0402C103J5RACTU)
C48  ValueDisplayed: 0.01uF  [0402]  (hidden comment: C0402C103J5RACTU)
C49  VDC_V: 10V  ValueDisplayed: 10uF  [0402_070]  (hidden comment: CL05A106MP5NUNC)
C50  VDC_V: 10V  ValueDisplayed: 10uF  [0402_070]  (hidden comment: CL05A106MP5NUNC)
C51  Cap_F: 4.7µF  VDC_V: 35V  [0805_HV]  (hidden comment: C2012X7R1V475M125AC)
C52  ValueDisplayed: 220pF  [0201_033]  (hidden comment: CGA1A2X7R1H221K030BA)
C53  ValueDisplayed: 220pF  [0201_033]  (hidden comment: CGA1A2X7R1H221K030BA)
C54  ValueDisplayed: 22uF  [0805_HV]  (hidden comment: C2012X5R1V226M125AC)
C55  ValueDisplayed: 22uF  [0805_HV]  (hidden comment: C2012X5R1V226M125AC)
C56  ValueDisplayed: 0.1uF  [0402]  (hidden comment: GMK105BJ104KV-F)
C57  ValueDisplayed: 0.1uF  [0402]  (hidden comment: GMK105BJ104KV-F)
C58  ValueDisplayed: 0.1µF  [0603]  (hidden comment: 0603YC104JAT2A)
C59  ValueDisplayed: 1uF  [1206]  (hidden comment: GRM31MR71H105KA88L)
C60  VDC_V: 10V  ValueDisplayed: 2.2uF  [0603]  (hidden comment: CGA3E3X5R1A225K080AB)
C61  ValueDisplayed: 10uF  [0603]  (hidden comment: C3225X5R1H106K250AB)
C62  ValueDisplayed: 0.22uF  [0603]  (hidden comment: C1608X5R1H224K080AB)
C63  ValueDisplayed: 0.1µF  [0402]  (hidden comment: GRM155R61H104ME14D)
C64  ValueDisplayed: 22uF  [0805_HV]  (hidden comment: GRM219R61C226ME15L)
C65  ValueDisplayed: 22uF  [0805_HV]  (hidden comment: GRM219R61C226ME15L)
C66  ValueDisplayed: 22uF  [0805_HV]  (hidden comment: GRM219R61C226ME15L)
C67  ValueDisplayed: 22uF  [0805_HV]  (hidden comment: GRM219R61C226ME15L)
C68  ValueDisplayed: 22uF  [0805_HV]  (hidden comment: GRM219R61C226ME15L)
D1  LW QH8G-Q2S2-3K5L-1  [LW QH8G_White]  (value not drawn)
J2  DX07S024JJ2R1300  [JAE_DX07S024JJ2R1300]  (value not drawn)
J4  TSW-104-07-G-S  [TSW-104-07-G-S]
L2  FBMJ2125HM210NT  [0805_HV]  (value not drawn)
L3  ValueDisplayed: 5.6uH  [SRP6540]  (hidden comment: SRP6540-5R6M)
R4  ValueDisplayed: 10k  [0402]  (hidden comment: CRCW040210K0JNED)
R23  ValueDisplayed: 0  [0402]  (hidden comment: RC0402JR-070RL)
R24  ValueDisplayed: 100k  [0402]  (hidden comment: RMCF0402FT100K)
R25  ValueDisplayed: 0  [0402]  (hidden comment: RC0402JR-070RL)
R27  ValueDisplayed: 0  [0402]  (hidden comment: RC0402JR-070RL)
R28  ValueDisplayed: 2.20k  [0402]  (hidden comment: CRCW04022K20FKED)
R29  ValueDisplayed: 2.20k  [0402]  (hidden comment: CRCW04022K20FKED)
R30  ValueDisplayed: 2.20k  [0402]  (hidden comment: CRCW04022K20FKED)
R31  ValueDisplayed: 2.20k  [0402]  (hidden comment: CRCW04022K20FKED)
R32  ValueDisplayed: 0  [0402]  (hidden comment: RC0402JR-070RL)
R33  ValueDisplayed: 0  [0402]  (hidden comment: RC0402JR-070RL)
R34  Parameter 1: DNP  [0402]  (hidden comment: CRCW040210K0JNED)
R35  Parameter 1: DNP  [0402]  (hidden comment: CRCW040210K0JNED)
R36  Parameter 1: DNP  [0402]  (hidden comment: CRCW040210K0JNED)
R39  ValueDisplayed: 0  [0402]  (hidden comment: RC0402JR-070RL)
R41  ValueDisplayed: 0  [0402]  (hidden comment: RC0402JR-070RL)
R42  ValueDisplayed: 10k  [0402]  (hidden comment: CRCW040210K0JNED)
R43  ValueDisplayed: 10k  [0402]  (hidden comment: CRCW040210K0JNED)
R44  ValueDisplayed: 10k  [0402]  (hidden comment: CRCW040210K0JNED)
R45  ValueDisplayed: 10k  [0402]  (hidden comment: CRCW040210K0JNED)
R46  ValueDisplayed: 0  [0402]  (hidden comment: RC0402JR-070RL)
R47  ValueDisplayed: 30  [0402]  (hidden comment: CRCW040230R0JNED)
R48  ValueDisplayed: 0  [0402]  (hidden comment: RC0402JR-070RL)
R49  ValueDisplayed: 52.3k  [0603]  (hidden comment: CRCW060352K3FKEA)
R50  ValueDisplayed: 10.0k  [0603]  (hidden comment: CRCW060310K0FKEA)
S1  CHS-01TB  [SW_CHS-01TB]  (value not drawn)
U2  TPS25750DRJK  [RJK0038B-C01-MFG]
U3  TVS2200DRVR  [DRV0006A]
U4  CAT24C256WI-G  [SOIC-8]
U5  TPS76333DBVR  [DBV0005A_N]
U6  TPS56339DDCR  [DDC0006A_N]

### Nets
GND: C44.2 C45.2 C46.2 C47.2 C48.2 C49.1 C50.1 C51.2 C52.2 C53.2 C54.2 C55.2 C56.2 C57.2 C58.1 C59.2 C60.2 C61.2 C62.2 C64.2 C65.2 C66.2 C67.2 C68.2 J2.A1(GND) J2.A12(GND) J2.B1(GND) J2.B12(GND) J2.S1(SHIELD) J2.S2(SHIELD) J2.S3(SHIELD) J2.S4(SHIELD) J4.3 R4.1 R24.1 R32.1 R33.1 R42.1 R43.1 R44.1 R45.1 R50.1 U2.5(GND) U2.11(GND) U2.12(GND) U2.14(GND) U2.31(GND) U2.39(GND_PAD) U3.1(GND) U3.2(GND) U3.3(GND) U3.7(PAD) U4.4(VSS) U5.2(GND) U6.1(GND)
ADCIN1: R23.2 S1.1 U2.2(ADCIN1) ; off-sheet ADCIN1
ADCIN2: R23.1 R24.2 U2.3(ADCIN2) ; off-sheet ADCIN2
BAT: C61.1 C62.1 R48.2 U6.3(VIN) ; off-sheet BAT
C_CC1: C53.1 J2.A5(CC1) U2.28(CC1) ; off-sheet C_CC1
C_CC2: C52.1 J2.B5(CC2) U2.29(CC2) ; off-sheet C_CC2
CBL_DIR: U2.36(CBL_DIR) ; off-sheet CBL_DIR
DTA_RLE: U2.10(DTA_RLE) ; off-sheet DTA_RLE
FLT_OCP: U2.13(~{FLT_OCP}) ; off-sheet FLT_OCP
I2C_SCL: R25.2 R28.2 R39.1 ; off-sheet I2C_SCL
I2C_SDA: R27.2 R29.2 R41.1 ; off-sheet I2C_SDA
I2CS_SCL: J4.2 R31.1 R33.2 U2.9(GND) ; off-sheet I2CS_SCL
I2CS_SDA: J4.1 R30.1 R32.2 U2.8(GND) ; off-sheet I2CS_SDA
LDO_1V5: C50.2 S1.2 U2.4(LDO_1V5) ; off-sheet LDO_1V5
LDO_3V3: C49.2 C57.1 C58.2 J4.4 R28.1 R29.1 R30.2 R31.2 R34.2 R35.2 R36.2 U2.1(LDO_3V3) U4.8(VCC) ; off-sheet LDO_3V3
P3V3: C44.1 C60.1 U2.38(VIN_3V3) U5.5(OUT) ; off-sheet P3V3
P5V0: C59.1 C64.1 C65.1 C66.1 C67.1 C68.1 L3.2 R46.2 R49.2 U2.34-35(PP5V) U5.1(IN) ; off-sheet P5V0
PPHV: C54.1 C55.1 C56.1 U2.20-21-22(PPHV) ; off-sheet PPHV
PWR_C0: U2.7(PWR_C0) ; off-sheet PWR_C0
PWR_C1: U2.19(PWR_C1) ; off-sheet PWR_C1
PWR_ERR: U2.18(PWR_ERR) ; off-sheet PWR_ERR
PWR_SRC: U2.6(PWR_SRC) ; off-sheet PWR_SRC
USB3: U2.37(USB3) ; off-sheet USB3
USB_N: J2.A7(Dn1) J2.B7(Dn2) U2.27(USB_N) ; off-sheet USB_N
USB_P: J2.A6(Dp1) J2.B6(Dp2) U2.26(USB_P) ; off-sheet USB_P
VBUS: C51.1 L2.2 U2.23-24-25(VBUS_IN) U2.32-33(VBUS) ; off-sheet VBUS
NetC45_1: C45.1 C46.1 C47.1 C48.1 D1.1(A) J2.A4(VBUS) J2.A9(VBUS) J2.B4(VBUS) J2.B9(VBUS) L2.1 U3.4(IN) U3.5(IN) U3.6(IN)
NetC63_1: C63.1 R47.2
NetC63_2: C63.2 L3.1 U6.2(SW)
NetD1_2: D1.2(K) R4.2
NetR25_1: R25.1 U2.17(I2C_SCL)
NetR27_1: R27.1 U2.16(I2C_SDA)
NetR34_1: R34.1 R43.2 U4.1(A0)
NetR35_1: R35.1 R44.2 U4.2(A1)
NetR36_1: R36.1 R45.2 U4.3(A2)
NetR39_2: R39.2 U4.6(SCL)
NetR41_2: R41.2 U4.5(SDA)
NetR42_2: R42.2 U4.7(WP)
NetR46_1: R46.1 U5.3(EN)
NetR47_1: R47.1 U6.6(BOOT)
NetR48_1: R48.1 U6.5(EN)
NetR49_1: R49.1 R50.2 U6.4(FB)
NetU2_15: U2.15(DRAIN) U2.30(DRAIN) U2.40(DRAIN_PAD)

Not connected (* = marked no-connect by the designer): J2 A2(SSTXp1)* A3(SSTXn1)* A8(SBU1)* A10(SSRXn2)* A11(SSRXp2)* B2(SSTXp2)* B3(SSTXn2)* B8(SBU2)* B10(SSRXn1)* B11(SSRXp1)*; U5 4(NC)*

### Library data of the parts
C44 C49 C50 = CMP-0006339-4: CAP, CERM, 10 uF, 10 V, +/- 20%, X5R, 0402; Manufacturer: Samsung Electro-Mechanics; TaMin_C: -55°C; Polarized: N; SizeAreaWB_mm2: 3; Value1: Unknown; U/M: EA; Value: 10uF; TaMax_C: 85°C; SizeZ_mm: 0.6; SizeX_mm: 1; SizeY_mm: 0.5; Cap_Case: 0402; Cap_F: 10µF; AEC Category: Q200
C45-C48 = CMP-0006236-2: CAP, CERM, 0.01 uF, 50 V, +/- 5%, X7R, 0402; Manufacturer: Kemet; TaMin_C: -55°C; Polarized: N; SizeAreaWB_mm2: 3; Value1: Unknown; U/M: EA; Value: 0.01uF; TaMax_C: 125°C; SizeZ_mm: 0.6; SizeX_mm: 1; SizeY_mm: 0.5; Value2: 50V; CompType: Capacitor; Cap_F: 10nF; AEC Category: Q200
C51 = CMP-0081100-1: CAP, CERM, 4.7 µF, 35 V,+/- 20%, X7R, 0805; Manufacturer: TDK; TaMin_C: -55°C; Polarized: N; SizeAreaWB_mm2: 6.75; U/M: EA; Value: 4.7uF; TaMax_C: 125°C; SizeZ_mm: 1.45; SizeX_mm: 2; SizeY_mm: 1.25; Cap_Case: 0805; SizeArea_mm2: 2.5; AEC Category: Q200
C52 C53 = CMP-0009652-3: CAP, CERM, 220 pF, 50 V, +/- 10%, X7R, AEC-Q200 Grade 1, 0201; Manufacturer: TDK; TaMin_C: -55°C; ESR_ohm: 11.6275; Polarized: N; SizeAreaWB_mm2: 2.08; Value1: 11.6275 ohm; U/M: EA; Value: 220pF; TaMax_C: 125°C; SizeZ_mm: 0.33; SizeX_mm: 0.6; SizeY_mm: 0.3; Value2: 50V; SizeArea_mm2: 0.18; AEC Qualified: Y; IRMS_A: 200.785mA; AEC Grade: 1; AEC Category: Q200
C54 C55 = CMP-0007844-2: CAP, CERM, 22 uF, 35 V, +/- 20%, X5R, 0805; Manufacturer: TDK; TaMin_C: -55°C; ESR_ohm: 2.05m; Polarized: N; SizeAreaWB_mm2: 6.75; Value1: 0.00205 ohm; U/M: EA; Value: 22uF; TaMax_C: 85°C; SizeZ_mm: 1.45; SizeX_mm: 2; SizeY_mm: 1.25; Cap_Case: 0805; Value2: 35V; SizeArea_mm2: 2.5; Cap_F: 22µF; IRMS_A: 4.55587A; AEC Category: Q200
C56 = CMP-0006370-2: CAP, CERM, 0.1 uF, 35 V, +/- 10%, X5R, 0402; Manufacturer: Taiyo Yuden; TaMin_C: -55°C; Polarized: N; SizeAreaWB_mm2: 3; Value1: Unknown; U/M: EA; Value: 0.1uF; TaMax_C: 85°C; SizeZ_mm: 0.6; SizeX_mm: 1; SizeY_mm: 0.5; Value2: 35V; Cap_F: 100nF; AEC Category: Q200
C57 = CMP-0006370-2: CAP, CERM, 0.1 uF, 35 V, +/- 10%, X5R, 0402; Manufacturer: Taiyo Yuden; TaMin_C: -55°C; Polarized: N; SizeAreaWB_mm2: 3; Value1: Unknown; U/M: EA; Value: 0.1uF; TaMax_C: 85°C; SizeZ_mm: 0.6; SizeX_mm: 1; SizeY_mm: 0.5; Value2: 35V; CompType: Capacitor; Cap_F: 100nF; AEC Category: Q200
C58 = 0603YC104JAT2A: as C43 on sheet BQ25731 Charger
C59 = CMP-0008992-2: CAP, CERM, 1 uF, 50 V, +/- 10%, X7R, 1206; Manufacturer: MuRata; TaMin_C: -55°C; Polarized: N; SizeAreaWB_mm2: 10.92; Value1: Unknown; U/M: EA; Value: 1uF; TaMax_C: 125°C; SizeZ_mm: 1.35; SizeX_mm: 3.2; SizeY_mm: 1.6; Value2: 50V; SizeArea_mm2: 5.12; Cap_F: 1µF; AEC Category: Q200
C60 = CMP-0007091-5: CAP, CERM, 2.2 uF, 10 V, +/- 10%, X5R, AEC-Q200 Grade 3, 0603; Manufacturer: TDK; TaMin_C: -55°C; Polarized: N; SizeAreaWB_mm2: 4.68; Value1: Unknown; U/M: EA; Value: 2.2uF; TaMax_C: 85°C; SizeZ_mm: 1; SizeX_mm: 1.6; SizeY_mm: 0.8; SizeArea_mm2: 1.28; AEC Qualified: Y; Cap_F: 2.2µF; AEC Grade: 3; AEC Category: Q200
C61 = CMP-0007344-5: CAP, CERM, 10 uF, 25 V, +/- 20%, X5R, 0603; Manufacturer: MuRata; PartNumber: GRM188R61E106MA73D; TaMin_C: -55°C; Polarized: N; SizeAreaWB_mm2: 4.68; Value1: Unknown; U/M: EA; Value: 10uF; TaMax_C: 85°C; SizeZ_mm: 1; SizeX_mm: 1.6; SizeY_mm: 0.8; Value2: 25V; SizeArea_mm2: 1.28; CompType: Capacitor; Cap_F: 10µF; AEC Category: Q200
C62 = CMP-0007013-5: CAP, CERM, 0.22 uF, 50 V, +/- 10%, X5R, 0603; Manufacturer: TDK; TaMin_C: -55°C; ESR_ohm: 0.021699; Polarized: N; SizeAreaWB_mm2: 4.68; Value1: 0.021699 ohm; U/M: EA; Value: 0.22uF; TaMax_C: 85°C; SizeZ_mm: 1; SizeX_mm: 1.6; SizeY_mm: 0.8; Value2: 50V; SizeArea_mm2: 1.28; Cap_F: 220nF; IRMS_A: 1.12496A; AEC Category: Q200
C63 = GRM155R61H104ME14D: CAP, CERM, 0.1 µF, 50 V,+/- 20%, X5R, 0402; Manufacturer: MuRata; Polarized: N; CompType: Capacitor; Value: 0.1uF; U/M: EA; Cap_F: 0.0000001; Tolerance_%: 20; VDC_V: 50; Value2: 50V; TaMin_C: -55; TaMax_C: 85; SizeArea_mm2: 0.5; SizeAreaWB_mm2: 3; SizeX_mm: 1; SizeZ_mm: 0.6; AEC Category: Q200
C64-C68 = CMP-0008203-2: CAP, CERM, 22 uF, 16 V, +/- 20%, X5R, 0805; Manufacturer: MuRata; TaMin_C: -55°C; Polarized: N; SizeAreaWB_mm2: 6.75; Value1: Unknown; U/M: EA; Value: 22uF; TaMax_C: 85°C; SizeZ_mm: 1.45; SizeX_mm: 2; SizeY_mm: 1.25; Cap_Case: 0805; Value2: 16V; SizeArea_mm2: 2.5; Cap_F: 22µF; AEC Category: Q200
D1 = CMP-0002919-2: LED, White, SMD; Manufacturer: OSRAM; Io_A: 5mA; Vr_V: 5V; Tjmax_C: 95°C; Value1: W; Angle: 120; Ir_A: 10nA; Vf_V: 2.8V
J2 = CMP-0085712-2: Receptacle, USB 3.1 Type C, R/A, Gold, SMT; Manufacturer: JAE Electronics; Current_A: 1.25A; Gender: Female; Voltage_V: 20V; Pitch_mm: 0.5; Row_Count: 2
J4 = TSW-104-07-G-S: as J1 on sheet BQ25731 Charger
L2 = CMP-0003375-1: Ferrite Bead, 21 ohm @ 100 MHz, 6 A, 0805; Manufacturer: Taiyo Yuden; ZTyp@100MHz_Ohm: 21; SizeAreaWB_mm2: 6.75; DCR_ohm: 4m; Value1: 0.004 ohm; Value: 21 ohm; Imax_A: 6A; SizeZ_mm: 1.45; SizeX_mm: 2; SizeY_mm: 1.25; SizeArea_mm2: 2.5
L3 = CMP-0056965-1: Inductor, Shielded, Ferrite, 5.6 uH, 5.5 A, 0.038 ohm, SMD; Manufacturer: Bourns; Isat: 6A @ 20% inductance drop; Irms: 5.5A @ 40C rise; Green_Lifecycle: Active; SizeAreaWB_mm2: 82.65; DCR_ohm: 0.038; Green_REACh: Passed; Value: 5.6uH; Imax_A: 5.5A; SizeZ_mm: 4; SizeX_mm: 7.5; SizeY_mm: 6.7; SizeArea_mm2: 50.25; Ind_H: 5.6µH; AEC Category: Q200
R4 = CMP-0026825-5: RES, 10 k, 5%, 0.063 W, AEC-Q200 Grade 0, 0402; Manufacturer: Vishay-Dale; Power_W: 63mW; TempCo: 200 ppm/C; Value_Code: 10k0; Value: 10k; EIA_Code: E24; SizeX_mm: 1; SizeY_mm: 0.5; SizeZ_mm: 0.6; Value2: 0.063W; AEC Qualified: Y; VDC_V: 50V; AEC Category: Q200; AEC Grade: 0
R23 R25 R27 R32 R33 R39 R41 R46 R48 = RC0402JR-070RL: RES, 0, 5%, 0.063 W, 0402; Manufacturer: Yageo America; CompType: Resistor; Value: 0; Value_Code: 0000; Tolerance_%: 5; Power_W: 0.063; Value2: 0.063W; VDC_V: 50; TempCo: 200 ppm/C; SizeArea_mm2: 0.5; SizeX_mm: 1; SizeZ_mm: 0.6; EIA_Code: E24; U/M: EA; AEC Category: Q200; Green_Lifecycle: Active; Green_REACh: Passed
R24 = CMP-0026753-1: RES, 100 k, 1%, 0.063 W, AEC-Q200 Grade 0, 0402; Manufacturer: Stackpole Electronics Inc; Power_W: 63mW; TempCo: 100 ppm/C; U/M: EA; Value: 100k; EIA_Code: E96; SizeX_mm: 1; SizeY_mm: 0.5; SizeZ_mm: 0.6; Value2: 0.063W; AEC Qualified: Y; VDC_V: 50V; AEC Grade: 0; AEC Category: Q200
R28-R31 = CRCW04022K20FKED: RES, 2.20 k, 1%, 0.063 W, 0402; Manufacturer: Vishay-Dale; CompType: Resistor; Value: 2.20k; Res_ohm: 2200; Value_Code: 2k20; Tolerance_%: 1; Power_W: 0.063; Value2: 0.063W; TempCo: 100 ppm/C; SizeArea_mm2: 0.5; SizeZ_mm: 0.6; U/M: EA; AEC Category: Q200
R34-R36 R42-R45 = CRCW040210K0JNED: RES, 10 k, 5%, 0.063 W, 0402; Manufacturer: Vishay-Dale; CompType: Resistor; Value: 10k; Res_ohm: 10000; Value_Code: 10k0; Tolerance_%: 5; Power_W: 0.063; Value2: 0.063W; VDC_V: 50; TempCo: 200 ppm/C; SizeArea_mm2: 0.5; SizeX_mm: 1; SizeZ_mm: 0.6; EIA_Code: E24; U/M: EA; AEC Category: Q200; Green_Lifecycle: Active; Green_REACh: Passed
R47 = CRCW040230R0JNED: RES, 30, 5%, 0.063 W, 0402; Manufacturer: Vishay-Dale; CompType: Resistor; Value: 30; Value_Code: 30R0; Tolerance_%: 5; Power_W: 0.063; Value2: 0.063W; VDC_V: 50; TempCo: 200 ppm/C; SizeArea_mm2: 0.5; SizeX_mm: 1; SizeZ_mm: 0.6; EIA_Code: E24; U/M: EA; AEC Category: Q200
R49 = CRCW060352K3FKEA: RES, 52.3 k, 1%, 0.1 W, 0603; Manufacturer: Vishay-Dale; CompType: Resistor; Value: 52.3k; Res_ohm: 52300; Value_Code: 52k3; Tolerance_%: 1; Power_W: 0.1; Value2: 0.1W; VDC_V: 75; TempCo: 100 ppm/C; SizeArea_mm2: 1.28; SizeX_mm: 1.6; SizeY_mm: 0.8; EIA_Code: E96; U/M: EA; AEC Category: Q200; Green_Lifecycle: Active; Green_REACh: Passed
R50 = CRCW060310K0FKEA: as R19 on sheet BQ25731 Charger
S1 = CMP-0002163-2: Switch, Slide, SPST, Top Slide, SMT; Manufacturer: Copal Electronics; CurrentRating_mA: 100A; SwitchFunction: Off-On; VDC_V: 6V; PositionCount: 1
U2 = CMP-0090338-2: USB Type-C and USB PD Controller with Integrated Power Switches Optimized for Power Applications; Manufacturer: Texas Instruments; Usb Standard: USB 3.0; TJmax_C: +175°C; AEC Category: Q200; CompType: IC; Number Of Ports: 1; TaMax_C: +105°C; TaMin_C: -40°C; Standoff Height: 0mm; AEC Qualified: No; Max Supply Voltage: 22V; SizeZ_mm: 0.8mm; Min Supply Voltage: 3V
U3 = CMP-0077834-1: 22-V Precision Surge Protection Clamp, DRV0006A (WSON-6); Alternate Manufacturer: Texas Instruments; SizeAreaWB_mm2: 9.0; SizeZ_mm: 0.8; SizeX_mm: 2.0; SizeArea_mm2: 4.0; CompType: IC; AEC Qualified: N; AEC Category: Q200
U4 = CMP-0005314-2: 256 kb I2C CMOS Serial EEPROM, SOIC-8; Manufacturer: ON Semiconductor; SizeAreaWB_mm2: 55.131; SizeZ_mm: 1.75; SizeX_mm: 5.99; SizeY_mm: 4.9; SizeArea_mm2: 29.351
U5 = CMP-0035539-1: Single Output LDO, 150 mA, Fixed 3.3 V Output, 2.7 to 10 V Input, with Low IQ, 5-pin SOT-23 (DBV), -40 to 125 degC, Green (RoHS & no Sb/Br); Manufacturer: Texas Instruments; Fixed Output Options(V): 3.3; SubFamily: Single Channel LDO; Vdo(Typ)(mV): 300; Accuracy(%): 3; Vin(Max)(V): 10; Iq(Typ)(mA): 0.08; Vin(Min)(V): 2.7; Iout(Max)(A): 0.15
U6 = CMP-0084209-1: 4.5-V to 24-V Input, 3-A Output Synchronous Step-Down Converter, DDC0006A (SOT-23-THIN-6); Alternate PartNumber: TPS56339DDCT; Alternate Manufacturer: Texas Instruments; SizeAreaWB_mm2: 10.4675; SizeZ_mm: 0.87; SizeX_mm: 1.65; SizeY_mm: 2.95; SizeArea_mm2: 4.8675; CompType: IC; AEC Qualified: N; AEC Category: Q200

## Sheet PMP41013_Hardware.SchDoc
size 431 x 279 mm; Date: Not shown in title block; ApprovedBy: Not shown in title block; CheckedBy: Not shown in title block; Author: Not shown in title block; CompanyName: Not shown in title block; Engineer: Not shown in title block; Organization: Not shown in title block; Address1: Not shown in title block; Address2: Not shown in title block; Address3: Not shown in title block; Address4: Not shown in title block; DocumentNumber: 3; Revision: Use project parameter SCH_Rev; SheetNumber: 3; SheetTotal: 3; PageSetup: Record=PageOptions¦CenterHorizontal=True¦CenterVertical=True¦PrintScale=1.00¦XCorrection=1.00¦YCorrection=1.00¦PrintKind=0¦BorderSize=5000000¦LeftOffset=0¦BottomOffset=0¦Orientation=2¦PaperLength=1000¦PaperWidth=1000¦Scale=100¦PaperSource=15¦PrintQuality=600¦MediaType=1¦DitherType=10¦PaperKind=Letter¦PrintScaleMode=1
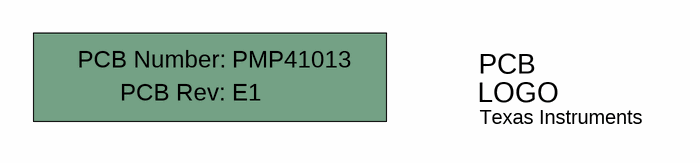
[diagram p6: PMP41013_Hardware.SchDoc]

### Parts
!PCB  Printed Circuit Board  (value not drawn)  (mechanical)
Logo1  Texas Instruments  [TI_Stacked_Overlay_Small]  (no BOM)

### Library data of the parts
!PCB = CMP-0003618-2: Manufacturer: Any; PartNumber: PMP41013
Logo1 = CMP-0074838-1: Texas Instrument Corporate Signature; SymbolCreator: a0412235; Lib Reference: TI_Logo; Library Reference: Logo

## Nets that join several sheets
GND: BQ25731 Charger (55 pins), TPS25750 USB PD Control (55 pins)
BAT: BQ25731 Charger (6 pins), TPS25750 USB PD Control (C61.1 C62.1 R48.2 U6.3)
I2C_SCL: BQ25731 Charger (J1.2 R15.1), TPS25750 USB PD Control (R25.2 R28.2 R39.1)
I2C_SDA: BQ25731 Charger (J1.1 R17.1), TPS25750 USB PD Control (R27.2 R29.2 R41.1)
LDO_3V3: BQ25731 Charger (C43.2 J1.4), TPS25750 USB PD Control (13 pins)
P3V3: BQ25731 Charger (R18.1), TPS25750 USB PD Control (C44.1 C60.1 U2.38 U5.5)
PPHV: BQ25731 Charger (11 pins), TPS25750 USB PD Control (C54.1 C55.1 C56.1 U2.20-21-22)

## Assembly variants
001: not fitted FID1 FID2 FID3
